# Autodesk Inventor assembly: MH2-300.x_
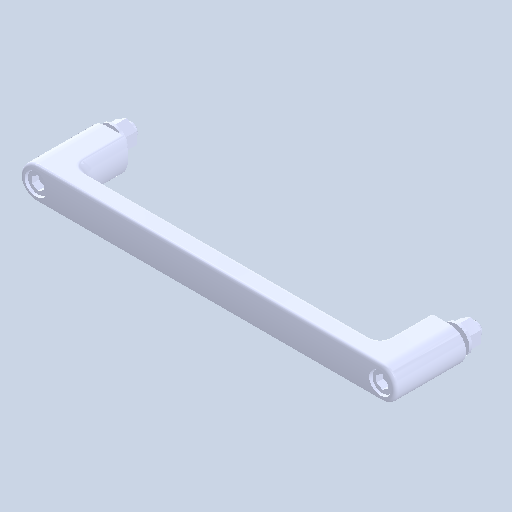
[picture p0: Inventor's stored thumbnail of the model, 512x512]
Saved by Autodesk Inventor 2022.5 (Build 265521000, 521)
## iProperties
Created: 2024-05
Part Number: MH2-300.x_
Document SubType Name: Assembly
Designer: ImaoCorp
Author: ImaoCorp
Sending System: SOLIDWORKS 2022-2022290
MC: AMD64
MC_MODEL: Intel64 Family 6 Model 60 Stepping 3, GenuineIntel
OS: Windows_NT
FRU: Parasolid Version 33.1, build 260,  4-25-2022
FORMAT: text
GUISE: transmit
KEY: FILEMH2-300.x_t
DATE: Fri May 31 16:17:52 2024
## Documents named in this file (4)
- Y:\5.更新分\2024年対応\0530_ROHDE\mh2\mh2-300\MH2-300.x_.iam
- Y:\5.更新分\2024年対応\0530_ROHDE\mh2\mh2-300\MH2-300_01.ipt
- Y:\5.更新分\2024年対応\0530_ROHDE\mh2\mh2-300\MH2-300_02.ipt
- Y:\5.更新分\2024年対応\0530_ROHDE\mh2\mh2-300\MH2-300_03.ipt
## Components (3 placed, 3 different names)
1. MH2-300_01
2. MH2-300_02
3. MH2-300_03
